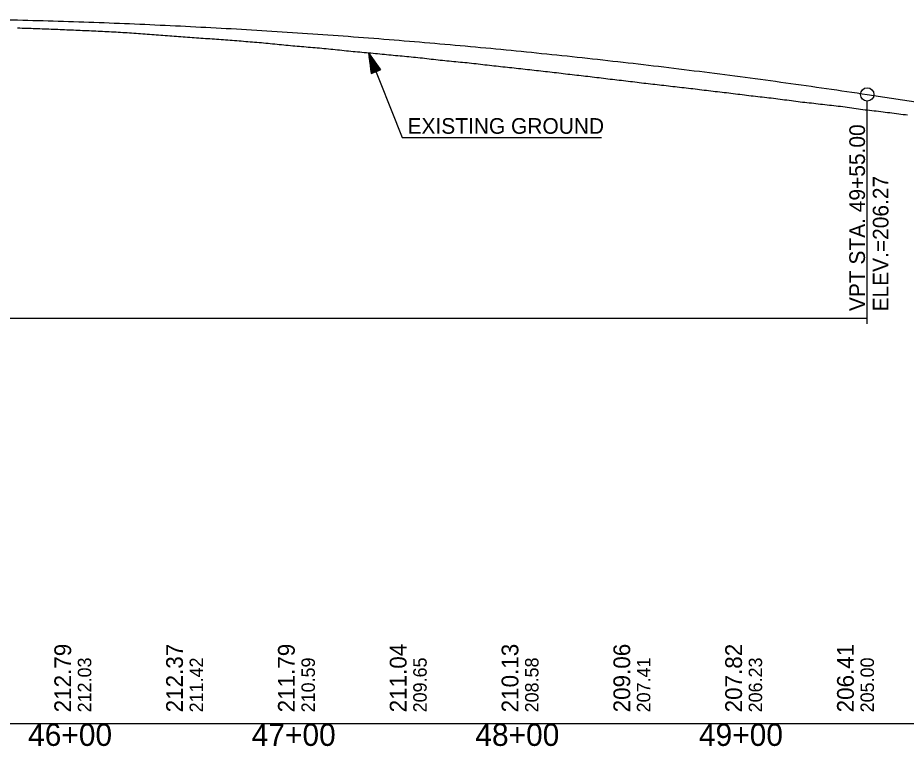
# Model space of a CAD drawing. Extents: x 69 to 2003113, y 512 to 837401.
# Drawn here: x 1891952.7 to 1892350, y 820540 to 820865.8 of the extents above; entities that cross this region are included whole.
import ezdxf

# ---------------------------------------------------------------- set-up
doc = ezdxf.new("R2010")
doc.units = 0
for name, color, linetype in [('BR_BORDER LINES', 7, 'Continuous'), ('BR_CONCRETE', 7, 'Continuous'), ('BR_GRID DOTS', 7, 'Continuous'), ('BR_GRID LINES', 7, 'Continuous'), ('BR_TEXT', 7, 'Continuous'), ('RD_HC_Points', 7, 'Continuous'), ('RD_PD_ALT1_TrvlWay', 7, 'Continuous'), ('RD_SHT_ID', 7, 'Continuous')]:
    doc.layers.add(name, color=color, linetype=linetype)

msp = doc.modelspace()

# ---------------------------------------------------------------- linework, layer by layer
at = {"layer": 'BR_BORDER LINES'}
msp.add_line((1889077.53, 820550.13), (1895477.53, 820550.13), dxfattribs=at)
at = {"layer": 'BR_GRID DOTS'}
for p, q in [((1892332.53, 820728.95), (1892332.53, 820828.45)), ((1891422.53, 820731.45), (1892332.53, 820731.45))]:
    msp.add_line(p, q, dxfattribs=at)
msp.add_circle((1892332.53, 820831.45), 3, dxfattribs=at)
at = {"layer": 'BR_GRID LINES'}
msp.add_line((1892332.53, 820831.45), (1892412.53, 820819.43), dxfattribs=at)
msp.add_spline([(1891422.53, 820831.86), (1891440.73, 820834.53), (1891458.93, 820837.08), (1891477.13, 820839.53), (1891495.33, 820841.87), (1891513.53, 820844.1), (1891531.73, 820846.22), (1891549.93, 820848.23), (1891568.13, 820850.13), (1891586.33, 820851.92), (1891604.53, 820853.6), (1891622.73, 820855.17), (1891640.93, 820856.64), (1891659.13, 820857.99), (1891677.33, 820859.24), (1891695.53, 820860.38), (1891713.73, 820861.41), (1891731.93, 820862.32), (1891750.13, 820863.13), (1891768.33, 820863.84), (1891786.53, 820864.43), (1891804.73, 820864.91), (1891822.93, 820865.28), (1891841.13, 820865.55), (1891859.33, 820865.7), (1891877.53, 820865.75), (1891895.73, 820865.69), (1891913.93, 820865.51), (1891932.13, 820865.23), (1891950.33, 820864.84), (1891968.53, 820864.34), (1891986.73, 820863.74), (1892004.93, 820863.02), (1892023.13, 820862.19), (1892041.33, 820861.26), (1892059.53, 820860.21), (1892077.73, 820859.06), (1892095.93, 820857.8), (1892114.13, 820856.42), (1892132.33, 820854.94), (1892150.53, 820853.35), (1892168.73, 820851.65), (1892186.93, 820849.84), (1892205.13, 820847.93), (1892223.33, 820845.9), (1892241.53, 820843.77), (1892259.73, 820841.52), (1892277.93, 820839.17), (1892296.13, 820836.7), (1892314.33, 820834.13), (1892332.53, 820831.45)], degree=3, dxfattribs=at)
at = {"layer": 'BR_TEXT'}
for points in [[(1891952.6, 820861.21), (1891953.6, 820861.18), (1891954.6, 820861.15), (1891955.6, 820861.12), (1891956.6, 820861.09), (1891957.6, 820861.06), (1891958.6, 820861.03), (1891959.6, 820861), (1891960.6, 820860.96), (1891961.6, 820860.93), (1891962.6, 820860.9), (1891963.6, 820860.87), (1891964.6, 820860.83), (1891965.6, 820860.79), (1891966.6, 820860.75), (1891967.6, 820860.71), (1891968.6, 820860.67), (1891969.6, 820860.63), (1891970.6, 820860.59), (1891971.6, 820860.55), (1891972.6, 820860.5), (1891973.6, 820860.46), (1891974.6, 820860.42), (1891975.6, 820860.38), (1891976.6, 820860.34), (1891977.6, 820860.29), (1891978.6, 820860.25), (1891979.6, 820860.21), (1891980.6, 820860.17), (1891981.6, 820860.13), (1891982.6, 820860.08), (1891983.6, 820860.04), (1891984.6, 820859.99), (1891985.6, 820859.95), (1891986.6, 820859.9), (1891987.6, 820859.85), (1891988.6, 820859.81), (1891989.6, 820859.76), (1891990.6, 820859.71), (1891991.6, 820859.67), (1891992.6, 820859.62), (1891993.6, 820859.57), (1891994.6, 820859.52), (1891995.6, 820859.46), (1891996.6, 820859.4), (1891997.6, 820859.34), (1891998.6, 820859.28), (1891999.6, 820859.22), (1892000.6, 820859.15), (1892001.6, 820859.09), (1892002.6, 820859.02), (1892003.6, 820858.95), (1892004.6, 820858.89)], [(1892004.6, 820858.89), (1892005.6, 820858.82), (1892006.6, 820858.75), (1892007.6, 820858.68), (1892008.6, 820858.61), (1892009.6, 820858.54), (1892010.6, 820858.47), (1892011.6, 820858.4), (1892012.6, 820858.32), (1892013.6, 820858.25), (1892014.6, 820858.17), (1892015.6, 820858.1), (1892016.6, 820858.02), (1892017.6, 820857.95), (1892018.6, 820857.87), (1892019.6, 820857.8), (1892020.6, 820857.73), (1892021.6, 820857.66), (1892022.6, 820857.59), (1892023.6, 820857.52), (1892024.6, 820857.45), (1892025.6, 820857.37), (1892026.6, 820857.29), (1892027.6, 820857.22), (1892028.6, 820857.14), (1892029.6, 820857.06), (1892030.6, 820856.98), (1892031.6, 820856.91), (1892032.6, 820856.83), (1892033.6, 820856.76), (1892034.6, 820856.69), (1892035.6, 820856.62), (1892036.6, 820856.55), (1892037.6, 820856.48), (1892038.6, 820856.42), (1892039.6, 820856.35), (1892040.6, 820856.28), (1892041.6, 820856.21), (1892042.6, 820856.14), (1892043.6, 820856.07), (1892044.6, 820856.01), (1892045.6, 820855.92), (1892046.6, 820855.84), (1892047.6, 820855.76), (1892048.6, 820855.68), (1892049.6, 820855.6), (1892050.6, 820855.52), (1892051.6, 820855.44), (1892052.6, 820855.37), (1892053.6, 820855.29), (1892054.6, 820855.21), (1892055.6, 820855.14), (1892056.6, 820855.06), (1892057.6, 820854.98), (1892058.6, 820854.9), (1892059.6, 820854.82), (1892060.6, 820854.72), (1892061.6, 820854.62), (1892062.6, 820854.52), (1892063.6, 820854.42), (1892064.6, 820854.32), (1892065.6, 820854.22), (1892066.6, 820854.12), (1892067.6, 820854.03), (1892068.6, 820853.94), (1892069.6, 820853.84), (1892070.6, 820853.74), (1892071.6, 820853.64), (1892072.6, 820853.53), (1892073.6, 820853.43), (1892074.6, 820853.35), (1892075.6, 820853.26), (1892076.6, 820853.18), (1892077.6, 820853.09), (1892078.6, 820853), (1892079.6, 820852.92), (1892080.6, 820852.83), (1892081.6, 820852.75), (1892082.6, 820852.66), (1892083.6, 820852.58), (1892084.6, 820852.49), (1892085.6, 820852.41), (1892086.6, 820852.32), (1892087.6, 820852.24), (1892088.6, 820852.15), (1892089.6, 820852.07), (1892090.6, 820851.99), (1892091.6, 820851.89), (1892092.6, 820851.78), (1892093.6, 820851.68), (1892094.6, 820851.58), (1892095.6, 820851.47), (1892096.6, 820851.37), (1892097.6, 820851.26), (1892098.6, 820851.16), (1892099.6, 820851.04), (1892100.6, 820850.93), (1892101.6, 820850.82), (1892102.6, 820850.73), (1892103.6, 820850.64), (1892104.6, 820850.55)], [(1892104.6, 820850.55), (1892105.6, 820850.45), (1892106.6, 820850.36), (1892107.6, 820850.27), (1892108.6, 820850.18), (1892109.6, 820850.09), (1892110.6, 820850), (1892111.6, 820849.9), (1892112.6, 820849.81), (1892113.6, 820849.71), (1892114.6, 820849.61), (1892115.6, 820849.52), (1892116.6, 820849.42), (1892117.6, 820849.32), (1892118.6, 820849.22), (1892119.6, 820849.13), (1892120.6, 820849.04), (1892121.6, 820848.95), (1892122.6, 820848.86), (1892123.6, 820848.77), (1892124.6, 820848.67), (1892125.6, 820848.57), (1892126.6, 820848.47), (1892127.6, 820848.38), (1892128.6, 820848.28), (1892129.6, 820848.18), (1892130.6, 820848.09), (1892131.6, 820847.98), (1892132.6, 820847.88), (1892133.6, 820847.78), (1892134.6, 820847.66), (1892135.6, 820847.55), (1892136.6, 820847.43), (1892137.6, 820847.31), (1892138.6, 820847.2), (1892139.6, 820847.08), (1892140.6, 820846.96), (1892141.6, 820846.85), (1892142.6, 820846.73), (1892143.6, 820846.62), (1892144.6, 820846.51), (1892145.6, 820846.42), (1892146.6, 820846.33), (1892147.6, 820846.24), (1892148.6, 820846.14), (1892149.6, 820846.05), (1892150.6, 820845.96), (1892151.6, 820845.87), (1892152.6, 820845.78), (1892153.6, 820845.68), (1892154.6, 820845.58), (1892155.6, 820845.47), (1892156.6, 820845.35), (1892157.6, 820845.24), (1892158.6, 820845.12), (1892159.6, 820845), (1892160.6, 820844.88), (1892161.6, 820844.76), (1892162.6, 820844.65), (1892163.6, 820844.54), (1892164.6, 820844.42), (1892165.6, 820844.31), (1892166.6, 820844.2), (1892167.6, 820844.1), (1892168.6, 820843.99), (1892169.6, 820843.88), (1892170.6, 820843.77), (1892171.6, 820843.66), (1892172.6, 820843.56), (1892173.6, 820843.45), (1892174.6, 820843.35), (1892175.6, 820843.24), (1892176.6, 820843.13), (1892177.6, 820843.02), (1892178.6, 820842.9), (1892179.6, 820842.78), (1892180.6, 820842.67), (1892181.6, 820842.55), (1892182.6, 820842.43), (1892183.6, 820842.31), (1892184.6, 820842.21), (1892185.6, 820842.11), (1892186.6, 820842.01), (1892187.6, 820841.9), (1892188.6, 820841.78), (1892189.6, 820841.67), (1892190.6, 820841.55), (1892191.6, 820841.44), (1892192.6, 820841.32), (1892193.6, 820841.21), (1892194.6, 820841.09), (1892195.6, 820840.96), (1892196.6, 820840.84), (1892197.6, 820840.72), (1892198.6, 820840.6), (1892199.6, 820840.49), (1892200.6, 820840.37), (1892201.6, 820840.26), (1892202.6, 820840.14), (1892203.6, 820840.03), (1892204.6, 820839.91)], [(1892204.6, 820839.91), (1892205.6, 820839.8), (1892206.6, 820839.69), (1892207.6, 820839.58), (1892208.6, 820839.46), (1892209.6, 820839.34), (1892210.6, 820839.21), (1892211.6, 820839.09), (1892212.6, 820838.97), (1892213.6, 820838.84), (1892214.6, 820838.72), (1892215.6, 820838.59), (1892216.6, 820838.47), (1892217.6, 820838.35), (1892218.6, 820838.24), (1892219.6, 820838.13), (1892220.6, 820838.02), (1892221.6, 820837.91), (1892222.6, 820837.8), (1892223.6, 820837.69), (1892224.6, 820837.56), (1892225.6, 820837.43), (1892226.6, 820837.31), (1892227.6, 820837.18), (1892228.6, 820837.06), (1892229.6, 820836.93), (1892230.6, 820836.81), (1892231.6, 820836.69), (1892232.6, 820836.57), (1892233.6, 820836.45), (1892234.6, 820836.33), (1892235.6, 820836.22), (1892236.6, 820836.12), (1892237.6, 820836.01), (1892238.6, 820835.9), (1892239.6, 820835.78), (1892240.6, 820835.67), (1892241.6, 820835.55), (1892242.6, 820835.43), (1892243.6, 820835.31), (1892244.6, 820835.19), (1892245.6, 820835.08), (1892246.6, 820834.97), (1892247.6, 820834.86), (1892248.6, 820834.75), (1892249.6, 820834.63), (1892250.6, 820834.52), (1892251.6, 820834.4), (1892252.6, 820834.28), (1892253.6, 820834.17), (1892254.6, 820834.05), (1892255.6, 820833.94), (1892256.6, 820833.81), (1892257.6, 820833.69), (1892258.6, 820833.56), (1892259.6, 820833.43), (1892260.6, 820833.31), (1892261.6, 820833.19), (1892262.6, 820833.07), (1892263.6, 820832.95), (1892264.6, 820832.84), (1892265.6, 820832.72), (1892266.6, 820832.6), (1892267.6, 820832.49), (1892268.6, 820832.37), (1892269.6, 820832.26), (1892270.6, 820832.14), (1892271.6, 820832.02), (1892272.6, 820831.9), (1892273.6, 820831.78), (1892274.6, 820831.66), (1892275.6, 820831.53), (1892276.6, 820831.41), (1892277.6, 820831.29), (1892278.6, 820831.16), (1892279.6, 820831.04), (1892280.6, 820830.91), (1892281.6, 820830.79), (1892282.6, 820830.67), (1892283.6, 820830.56), (1892284.6, 820830.45), (1892285.6, 820830.34), (1892286.6, 820830.22), (1892287.6, 820830.11), (1892288.6, 820830), (1892289.6, 820829.9), (1892290.6, 820829.79), (1892291.6, 820829.69), (1892292.6, 820829.55), (1892293.6, 820829.41), (1892294.6, 820829.26), (1892295.6, 820829.12), (1892296.6, 820828.98), (1892297.6, 820828.83), (1892298.6, 820828.69), (1892299.6, 820828.56), (1892300.6, 820828.43), (1892301.6, 820828.31), (1892302.6, 820828.19), (1892303.6, 820828.08), (1892304.6, 820827.97)], [(1892304.6, 820827.97), (1892305.6, 820827.87), (1892306.6, 820827.76), (1892307.6, 820827.65), (1892308.6, 820827.54), (1892309.6, 820827.43), (1892310.6, 820827.31), (1892311.6, 820827.18), (1892312.6, 820827.06), (1892313.6, 820826.94), (1892314.6, 820826.83), (1892315.6, 820826.73), (1892316.6, 820826.62), (1892317.6, 820826.51), (1892318.6, 820826.4), (1892319.6, 820826.29), (1892320.6, 820826.16), (1892321.6, 820826.04), (1892322.6, 820825.89), (1892323.6, 820825.73), (1892324.6, 820825.57), (1892325.6, 820825.41), (1892326.6, 820825.26), (1892327.6, 820825.14), (1892328.6, 820825.02), (1892329.6, 820824.89), (1892330.6, 820824.77), (1892331.6, 820824.65), (1892332.6, 820824.53), (1892333.6, 820824.41), (1892334.6, 820824.29), (1892335.6, 820824.17), (1892336.6, 820824.06), (1892337.6, 820823.94), (1892338.6, 820823.82), (1892339.6, 820823.7), (1892340.6, 820823.58), (1892341.6, 820823.46), (1892342.6, 820823.33), (1892343.6, 820823.2), (1892344.6, 820823.07), (1892345.6, 820822.94), (1892346.6, 820822.8), (1892347.6, 820822.67), (1892348.6, 820822.54), (1892349.6, 820822.42), (1892350.6, 820822.29)]]:
    msp.add_lwpolyline(points, dxfattribs=at)
at = {"layer": 'RD_PD_ALT1_TrvlWay'}
for p, q in [((1892109.54, 820850.09), (1892124.5, 820812.14)), ((1892112.84, 820841.72), (1892109.54, 820850.09)), ((1892109.54, 820850.09), (1892114.93, 820842.54)), ((1892109.54, 820850.09), (1892110.74, 820840.89)), ((1892110.74, 820840.89), (1892114.93, 820842.54)), ((1892124.5, 820812.14), (1892213.69, 820812.14))]:
    msp.add_line(p, q, dxfattribs=at)
for points in [[(1892112.74, 820841.8), (1892109.66, 820849.59), (1892112.7, 820841.73), (1892109.74, 820849.2), (1892112.6, 820841.73), (1892109.76, 820848.93), (1892112.49, 820841.7), (1892109.79, 820848.6), (1892112.41, 820841.65), (1892109.87, 820848.11), (1892112.3, 820841.59), (1892109.95, 820847.59), (1892112.18, 820841.58), (1892110.01, 820847.19), (1892112.1, 820841.53), (1892110.07, 820846.73), (1892111.99, 820841.55), (1892110.13, 820846.33), (1892111.94, 820841.44), (1892110.16, 820845.99), (1892111.8, 820841.43), (1892110.22, 820845.49), (1892111.7, 820841.37), (1892110.33, 820844.89), (1892111.61, 820841.31), (1892110.34, 820844.48), (1892111.5, 820841.27), (1892110.43, 820843.85), (1892111.38, 820841.27), (1892110.52, 820843.35), (1892111.28, 820841.17), (1892110.58, 820842.91), (1892111.18, 820841.17), (1892110.62, 820842.5), (1892111.1, 820841.07), (1892110.69, 820842.01), (1892110.99, 820841.11), (1892110.77, 820841.46), (1892110.87, 820841.1)], [(1892109.81, 820849.57), (1892112.86, 820841.85), (1892109.97, 820849.32), (1892112.96, 820841.89), (1892110.13, 820849.08), (1892113.04, 820841.88), (1892110.31, 820848.87), (1892113.11, 820841.92), (1892110.51, 820848.61), (1892113.2, 820841.94), (1892110.69, 820848.36), (1892113.27, 820841.97), (1892110.91, 820848.06), (1892113.36, 820841.99), (1892111.15, 820847.7), (1892113.48, 820842.05), (1892111.36, 820847.38), (1892113.56, 820842.04), (1892111.59, 820847.05), (1892113.64, 820842.09), (1892111.83, 820846.74), (1892113.73, 820842.13), (1892112.06, 820846.4), (1892113.78, 820842.21), (1892112.38, 820845.94), (1892113.88, 820842.21), (1892112.62, 820845.65), (1892113.96, 820842.2), (1892112.91, 820845.27), (1892114.03, 820842.27), (1892113.15, 820844.86), (1892114.13, 820842.33), (1892113.37, 820844.55), (1892114.21, 820842.42), (1892113.62, 820844.27), (1892114.28, 820842.45), (1892113.91, 820843.8), (1892114.43, 820842.43), (1892114.09, 820843.53), (1892114.57, 820842.48), (1892114.28, 820843.37), (1892114.67, 820842.62), (1892114.79, 820842.57), (1892114.64, 820842.61)]]:
    msp.add_lwpolyline(points, dxfattribs=at)

# ---------------------------------------------------------------- texts
at = {"layer": 'BR_CONCRETE'}
for s, height, p in [('VPT STA. 49+55.00 ', 7, (1892331.53, 820734.58)), ('ELEV.=206.27', 7, (1892342.03, 820734.41)), ('212.03', 6, (1891985.53, 820555.13)), ('211.42', 6, (1892035.53, 820555.13)), ('210.59', 6, (1892085.53, 820555.13)), ('209.65', 6, (1892135.53, 820555.13)), ('208.58', 6, (1892185.53, 820555.13)), ('207.41', 6, (1892235.53, 820555.13)), ('206.23', 6, (1892285.53, 820555.13)), ('205.00', 6, (1892335.53, 820555.13))]:
    msp.add_text(s, height=height, rotation=90, dxfattribs=at).set_placement(p)
at = {"layer": 'RD_HC_Points'}
for s, p in [('212.79', (1891976.53, 820555.13)), ('212.37', (1892026.53, 820555.13)), ('211.79', (1892076.53, 820555.13)), ('211.04', (1892126.53, 820555.13)), ('210.13', (1892176.53, 820555.13)), ('209.06', (1892226.53, 820555.13)), ('207.82', (1892276.53, 820555.13)), ('206.41', (1892326.53, 820555.13))]:
    msp.add_text(s, height=7.5, rotation=90, dxfattribs=at).set_placement(p)
at = {"layer": 'RD_PD_ALT1_TrvlWay'}
msp.add_text('EXISTING GROUND', height=7, dxfattribs=at).set_placement((1892126.96, 820813.87))
at = {"layer": 'RD_SHT_ID'}
for s, p in [('46+00', (1891957.29, 820540.13)), ('47+00', (1892057.29, 820540.13)), ('48+00', (1892157.29, 820540.13)), ('49+00', (1892257.29, 820540.13))]:
    msp.add_text(s, height=10, dxfattribs=at).set_placement(p)

doc.saveas('drawing.dxf')
